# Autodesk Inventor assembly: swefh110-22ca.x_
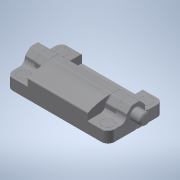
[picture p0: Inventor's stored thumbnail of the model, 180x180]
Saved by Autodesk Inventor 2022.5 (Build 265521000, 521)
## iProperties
Part Number: swefh110-22ca.x_
Material: 一般
Document SubType Name: Assembly
Designer: ImaoCorp
Sending System: SOLIDWORKS 2017-2017317
MC: AMD64
MC_MODEL: Intel64 Family 6 Model 60 Stepping 3, GenuineIntel
OS: Windows_NT
FRU: Parasolid Version 29.0, build 201,  4-17-2017
FORMAT: text
GUISE: transmit
KEY: swefh110-22ca
FILE: swefh110-22ca.x_t
DATE: Wed Sep 18 16:02:32 2019
Author: ImaoCorp
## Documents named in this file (3)
- X:\14_SW2022-Inv2022\00_全2023-1023新製品(TCC)まで\s\swefh110-22ca\SWEFH110-22CA.iam
- X:\14_SW2022-Inv2022\00_全2023-1023新製品(TCC)まで\s\swefh110-22ca\swefh110-22ca_01.ipt
- X:\14_SW2022-Inv2022\00_全2023-1023新製品(TCC)まで\s\swefh110-22ca\swefh110-22ca_02.ipt
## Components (2 placed, 2 different names)
1. swefh110-22ca_01
2. swefh110-22ca_02
